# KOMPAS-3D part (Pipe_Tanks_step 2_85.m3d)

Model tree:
1. X Axis
2. Y Axis
3. Z Axis  (labels: Bend 90 Dn 50; Pipe Dn 50)
     Òîëùèíà ñòåíêè 1 = 1

Referenced files in C:\Documents and Settings\kashirsky\Мои документы\Camtasia Studio\Pipelines3D\Tanks\: Tanks_step 4.a3d
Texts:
  Pipe Dn 50
  Steel ASTM A295
  Three Point Plane
  Plane at Angle
  Line and Point Plane
  Axis through Two Vertices
  Axis of Feature
  Axis of Conical Surface
  Axis through Edge
  Trim by Surface
  Trim by Sketch
  Feature with No History
  Intersection Axis of Two Planes
  Two Line Plane
  Line and Face Plane
  Bend by line
  Hole in sheet body
  Cut in sheet body
  Point in CM
  Linear Dimension from Line to Point
  Surface Finish Symbol
  Geometric Tolerance Symbol
  Leader #1
  Leader #2
  Leader #3
  Shape Deviations and Datum
  Node point number
  Mark of coordination axis
  Node point designation
  Mark/Reference designation with leader
  Mark/reference designation on line
  Mark/Reference designation without leader
  Bend 90 Dn 50
  Plane of section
